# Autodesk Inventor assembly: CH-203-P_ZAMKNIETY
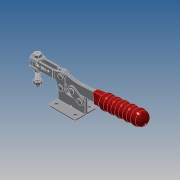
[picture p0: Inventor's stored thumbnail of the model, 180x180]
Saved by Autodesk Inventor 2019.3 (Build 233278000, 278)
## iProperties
Company: Î¢ÈíÖÐ¹ú
Created: 2015-08
Part Number: CH-203-P_ZAMKNIETY
Material: Ogólny
Description: STEP AP203
Document SubType Name: Assembly
Designer: CADENGINEERING4
Sending System: SolidWorks 2012
Preprocessor: SwSTEP 2.0
Title: CH-203-P.STEP
Author: Î¢ÈíÓÃ»§
Revision Number: ÈÎºÎ
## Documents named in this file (9)
- E:\STRONA\Horizontal toggle clamp\CH-203-P\CH-203-P_ZAMKNIETY.iam
- E:\STRONA\Horizontal toggle clamp\CH-203-P\203-P-01.ipt
- E:\STRONA\Horizontal toggle clamp\CH-203-P\203-P-02.ipt
- E:\STRONA\Horizontal toggle clamp\CH-203-P\225-D-06.ipt
- E:\STRONA\Horizontal toggle clamp\CH-203-P\FW516.ipt
- E:\STRONA\Horizontal toggle clamp\CH-203-P\56212-02.ipt
- E:\STRONA\Horizontal toggle clamp\CH-203-P\085012.ipt
- E:\STRONA\Horizontal toggle clamp\CH-203-P\02.iam
- E:\STRONA\Horizontal toggle clamp\CH-203-P\203-F-04.ipt
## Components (14 placed, 14 different names)
1. 203-P-01_1 — Zestawiające:10, Zestawiające:11, Zestawiające:12, Zestawiające:13, Zestawiające:14, Zestawiające:21, Zestawiające:26, Przejściowe:1
2. 203-P-02_2 — Równoległe:1, Zestawiające:5, Zestawiające:6, Zestawiające:9, Zestawiające:23, Zestawiające:24, Zestawiające:25, Zestawiające:26, Zestawiające:27
3. 225-D-06_3 — Zestawiające:21, Zestawiające:27
4. FW516_4 — Równoległe:1, Równoległe:2, Zestawiające:3, Zestawiające:6, Zestawiające:7
5. FW516_5 — Równoległe:2, Zestawiające:4, Zestawiające:5, Zestawiające:8
6. 56212-02_6 — Równoległe:3, Zestawiające:1, Zestawiające:7
7. 56212-02_7 — Zestawiające:2, Zestawiające:8
8. 085012_8 — Równoległe:3, Zestawiające:1, Zestawiające:2, Zestawiające:3, Zestawiające:4, Zestawiające:9
9. 02_9 [sub-assembly] — Zestawiające:19, Zestawiające:20, Zestawiające:22, Zestawiające:24, Przejściowe:1
10. 203-F-04_10 — Zestawiające:11, Zestawiające:13, Zestawiające:16
11. 203-F-04_11 — Zestawiające:10, Zestawiające:12, Zestawiające:15, Zestawiające:16, Zestawiające:17, Zestawiające:18, Zestawiające:19
12. 225-D-06_12 — Zestawiające:22, Zestawiające:23, Zestawiające:25
13. 225-D-06_13 — Zestawiające:17, Zestawiające:18, Zestawiające:20
14. 225-D-06_14 — Zestawiające:14, Zestawiające:15
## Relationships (31: Mate 27, Flush 3, Transitional 1)
- Równoległe:1 [Flush]: 203-P-02_2 ↔ FW516_4
- Równoległe:2 [Flush]: FW516_4 ↔ FW516_5
- Równoległe:3 [Flush]: 56212-02_6 ↔ 085012_8
- Zestawiające:1 [Mate]: 56212-02_6 ↔ 085012_8
- Zestawiające:2 [Mate]: 56212-02_7 ↔ 085012_8
- Zestawiające:3 [Mate]: FW516_4 ↔ 085012_8
- Zestawiające:4 [Mate]: FW516_5 ↔ 085012_8
- Zestawiające:5 [Mate]: 203-P-02_2 ↔ FW516_5
- Zestawiające:6 [Mate]: 203-P-02_2 ↔ FW516_4
- Zestawiające:7 [Mate]: FW516_4 ↔ 56212-02_6
- Zestawiające:8 [Mate]: FW516_5 ↔ 56212-02_7
- Zestawiające:9 [Mate]: 203-P-02_2 ↔ 085012_8
- Zestawiające:10 [Mate]: 203-P-01_1 ↔ 203-F-04_11
- Zestawiające:11 [Mate]: 203-P-01_1 ↔ 203-F-04_10
- Zestawiające:12 [Mate]: 203-P-01_1 ↔ 203-F-04_11
- Zestawiające:13 [Mate]: 203-P-01_1 ↔ 203-F-04_10
- Zestawiające:14 [Mate]: 203-P-01_1 ↔ 225-D-06_14
- Zestawiające:15 [Mate]: 203-F-04_11 ↔ 225-D-06_14
- Zestawiające:16 [Mate]: 203-F-04_10 ↔ 203-F-04_11
- Zestawiające:17 [Mate]: 203-F-04_11 ↔ 225-D-06_13
- Zestawiające:18 [Mate]: 203-F-04_11 ↔ 225-D-06_13
- Zestawiające:19 [Mate]: 02_9 ↔ 203-F-04_11
- Zestawiające:20 [Mate]: 02_9 ↔ 225-D-06_13
- Zestawiające:21 [Mate]: 203-P-01_1 ↔ 225-D-06_3
- Zestawiające:22 [Mate]: 02_9 ↔ 225-D-06_12
- Zestawiające:23 [Mate]: 203-P-02_2 ↔ 225-D-06_12
- Zestawiające:24 [Mate]: 203-P-02_2 ↔ 02_9
- Zestawiające:25 [Mate]: 203-P-02_2 ↔ 225-D-06_12
- Zestawiające:26 [Mate]: 203-P-01_1 ↔ 203-P-02_2
- Zestawiające:27 [Mate]: 203-P-02_2 ↔ 225-D-06_3
- Przejściowe:1 [Transitional]: 203-P-01_1 ↔ 02_9
